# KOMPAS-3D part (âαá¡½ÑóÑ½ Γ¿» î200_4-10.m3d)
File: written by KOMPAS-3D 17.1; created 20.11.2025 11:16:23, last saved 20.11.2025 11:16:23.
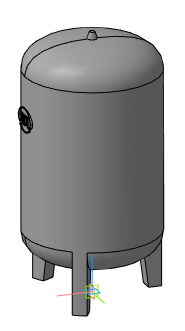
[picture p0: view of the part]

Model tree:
1. Операция без истории:3

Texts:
  REVIT MATERIAL OVERRIDDEN
  REVIT MATERIAL ID
  REVIT SUBCATEGORY ID
  REVIT CATEGORY ID
  REVIT ELEMENT ID
  REVIT BREP TAG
